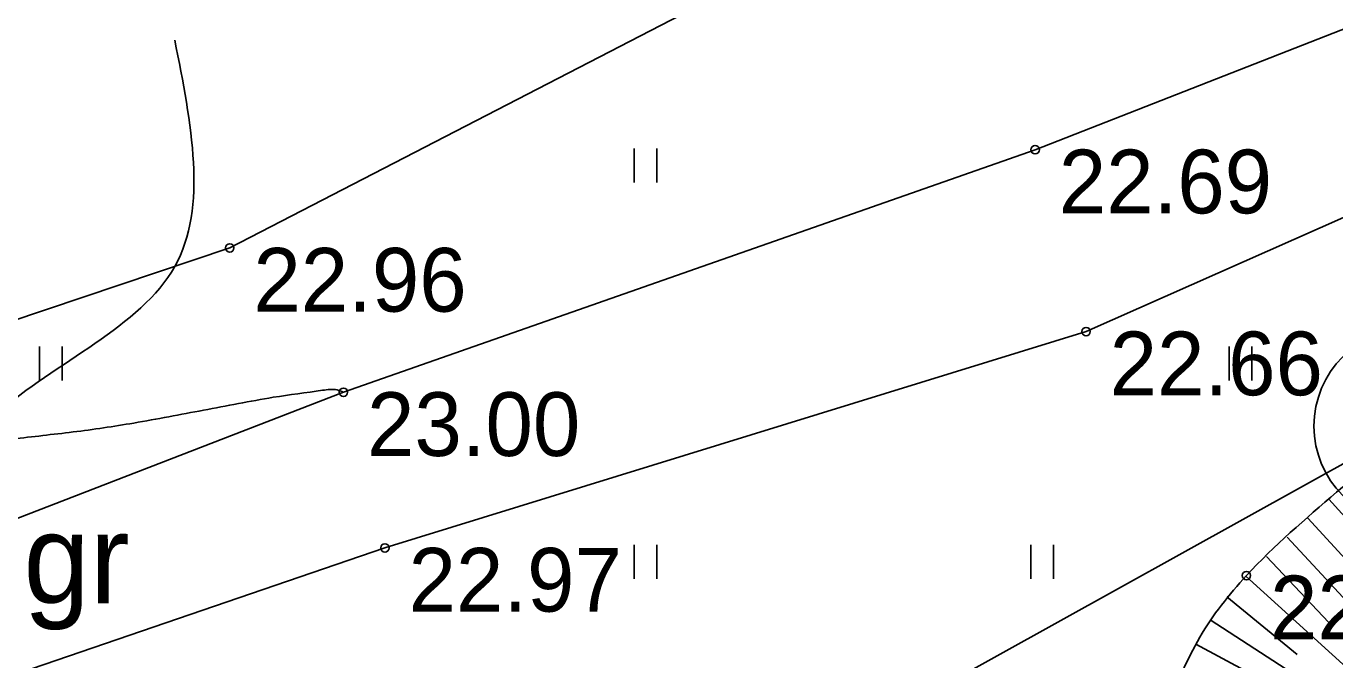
# Model space of a CAD drawing. Extents: x 521824 to 524158, y 294774 to 296228.
# Drawn here: x 521968.76 to 521991.87, y 295983.07 to 295994.26 of the extents above; entities that cross this region are included whole.
import ezdxf

# ---------------------------------------------------------------- set-up
doc = ezdxf.new("R2010")
doc.units = 0
for name, color, linetype in [('CELI_CMAL_####_####_#', 7, 'Continuous'), ('CELI_CSEG_####_TKST_#', 7, 'Continuous'), ('GL Atradnes kontura', 7, 'Continuous'), ('GL Atradnes Robezpunkti', 7, 'Continuous'), ('HIDG_HORZ_RESN_####_#', 7, 'Continuous'), ('RAMI_UZMR_####_####_#', 7, 'Continuous'), ('RELJ_AATZ_####_TKST_#', 7, 'Continuous'), ('RELJ_ELEM_####_####_#', 7, 'Continuous'), ('RELJ_HORZ_PAMT_####_#', 7, 'Continuous'), ('RELJ_NOGA_####_####_#', 7, 'Continuous'), ('TERT_ELEM_####_####_#', 7, 'Continuous')]:
    doc.layers.add(name, color=color, linetype=linetype)

msp = doc.modelspace()

# ---------------------------------------------------------------- linework, layer by layer
at = {"layer": 'CELI_CMAL_####_####_#'}
for points in [[(522016.926, 296038.306), (522019.291, 296036.109), (522026.144, 296024.408), (522024.611, 296016.559), (522016.21, 296007.977), (522009.446, 296002.958), (521998.646, 295996.811), (521986.577, 295992.078), (521974.364, 295987.793), (521962.15, 295983.065), (521949.049, 295978.089), (521936.439, 295973.322), (521922.423, 295968.209), (521916.609, 295966.986)], [(521919.307, 295961.099), (521923.436, 295965.418), (521936.98, 295970.41), (521950.344, 295975.897), (521962.84, 295980.846), (521975.098, 295985.044), (521987.475, 295988.865), (521999.923, 295994.382), (522010.781, 296000.817), (522017.822, 296005.998), (522028.512, 296014.094), (522032.708, 296013.095), (522037.117, 296005.565), (522042.629, 295993.246), (522047.854, 295977.085), (522048.272, 295975.108), (522050.6, 295963.95), (522058.017, 295953.029), (522071.017, 295938.84), (522077.076, 295928.039), (522079.604, 295917.159), (522079.604, 295917.159)]]:
    msp.add_lwpolyline(points, dxfattribs=at)
at = {"layer": 'GL Atradnes kontura'}
msp.add_lwpolyline([(521873.3, 295920.729), (521993.224, 295987.196), (522041.36, 296024.307), (522231.747, 296043.148), (522231.747, 296043.148), (522324.238, 295937.68), (522172.848, 295833.392), (522160.802, 295825.572), (522154.447, 295832.015), (522095.923, 295791.504), (521999.655, 295722.606), (521986.667, 295713.792), (521905.108, 295850.089)], close=True, dxfattribs=at)
at = {"layer": 'GL Atradnes Robezpunkti'}
msp.add_circle((521993.224, 295987.196), 1.725, dxfattribs=at)
at = {"layer": 'HIDG_HORZ_RESN_####_#'}
msp.add_spline([(521991.098, 295970.584), (521991.361, 295971.278), (521991.544, 295971.992), (521991.631, 295972.636), (521991.67, 295973.287), (521991.708, 295973.937), (521991.792, 295974.583), (521992.63, 295977.225), (521993.211, 295978.366), (521993.867, 295979.444), (521995.485, 295981.37), (521997.019, 295982.765), (521998.585, 295984.11), (522000.189, 295985.403), (522001.836, 295986.644), (522003.976, 295988.175), (522005.153, 295988.977), (522005.573, 295989.274), (522005.842, 295989.418), (522006.142, 295989.64), (522006.471, 295989.666), (522006.478, 295989.599), (522006.466, 295989.526), (522006.399, 295989.37), (522006.201, 295989.063), (522005.975, 295988.711), (522005.731, 295988.372), (522004.942, 295987.535), (522004.639, 295987.117), (522004.481, 295986.733), (522004.423, 295986.398), (522004.378, 295986.007), (522004.399, 295985.686), (522004.471, 295985.525), (522004.59, 295985.595), (522004.709, 295985.673), (522004.948, 295985.833), (522005.409, 295986.135), (522005.803, 295986.452), (522006.182, 295986.785), (522006.909, 295987.485), (522008.327, 295988.922), (522009.25, 295989.823), (522010.176, 295990.722), (522012.8, 295992.885), (522014.764, 295994.23), (522015.821, 295994.628), (522016.98, 295994.792), (522018.134, 295994.975), (522019.175, 295995.425), (522019.869, 295995.953), (522020.532, 295996.498), (522021.781, 295997.642), (522022.943, 295998.856), (522024.04, 296000.142), (522024.659, 296000.936), (522025.232, 296001.756), (522025.813, 296002.577), (522026.455, 296003.378), (522027.623, 296004.465), (522028.262, 296004.882), (522028.898, 296005.162), (522029.797, 296005.281)], degree=3, dxfattribs=at)
at = {"layer": 'RAMI_UZMR_####_####_#'}
msp.add_lwpolyline([(521884.951, 295833.479), (521880.617, 295845.248), (521870.086, 295867.104), (521860.21, 295884.107), (521842.62, 295911.756), (521831.61, 295926.961), (521828.312, 295927.865), (521830.005, 295934.14), (521828.66, 295939.141), (521854.064, 295946.907), (521876.684, 295957.669), (521889.204, 295963.079), (521933.742, 295979.544), (521953.527, 295984.007), (521972.358, 295990.342), (521984.5, 295996.619), (522023.729, 296021.723)], dxfattribs=at)
at = {"layer": 'RELJ_ELEM_####_####_#'}
for centre in [(521986.577, 295992.078), (521972.358, 295990.342), (521987.475, 295988.865), (521974.364, 295987.793), (521975.098, 295985.044), (521990.306, 295984.555)]:
    msp.add_circle(centre, 0.075, dxfattribs=at)
at = {"layer": 'RELJ_HORZ_PAMT_####_#'}
msp.add_spline([(521971.387, 295994.015), (521971.387, 295990.015), (521968.248, 295987.412), (521968.164, 295987.335), (521968.083, 295987.24), (521968.053, 295987.069), (521968.165, 295987.012), (521968.282, 295986.979), (521968.52, 295986.973), (521969.057, 295987.029), (521969.593, 295987.092), (521970.129, 295987.165), (521970.663, 295987.25), (521971.28, 295987.361), (521971.895, 295987.477), (521972.51, 295987.593), (521973.127, 295987.704), (521973.996, 295987.828), (521974.255, 295987.834), (521974.364, 295987.793)], degree=3, dxfattribs=at)
at = {"layer": 'RELJ_NOGA_####_####_#'}
for p, q in [((521991.763, 295985.907), (521995.223, 295982.049)), ((521991.392, 295985.572), (521992.449, 295984.415)), ((521991.025, 295985.233), (521994.607, 295981.372)), ((521990.66, 295984.892), (521991.755, 295983.736)), ((521990.298, 295984.547), (521994.243, 295980.961)), ((521989.96, 295984.178), (521991.201, 295983.163)), ((521989.667, 295983.774), (521994.156, 295980.862)), ((521989.415, 295983.342), (521990.825, 295982.584))]:
    msp.add_line(p, q, dxfattribs=at)
msp.add_spline([(522004.959, 295994.763), (522004.669, 295994.618), (522001.953, 295993.298), (521999.283, 295991.897), (521997.991, 295991.121), (521997.361, 295990.706), (521996.743, 295990.27), (521995.097, 295988.9), (521993.516, 295987.455), (521991.899, 295986.028), (521990.306, 295984.555), (521989.484, 295983.468), (521988.925, 295982.206), (521988.502, 295980.867), (521988.303, 295980.201), (521988.089, 295979.552), (521987.627, 295977.511), (521987.453, 295975.366), (521987.309, 295973.233), (521987.176, 295972.225), (521987.068, 295971.725), (521986.936, 295971.227), (521986.631, 295970.771), (521986.092, 295970.469), (521984.613, 295970.296), (521983.113, 295970.636), (521982.547, 295970.976), (521982.204, 295971.417), (521982.165, 295971.604), (521982.175, 295971.806), (521982.331, 295972.172), (521982.97, 295972.974), (521983.604, 295973.781), (521983.714, 295974.554), (521983.324, 295975.398), (521982.883, 295976.235), (521982.376, 295977.059), (521981.79, 295977.861)], degree=3, dxfattribs=at)
at = {"layer": 'TERT_ELEM_####_####_#'}
for p, q in [((521979.5, 295991.5), (521979.5, 295992.1)), ((521979.9, 295991.5), (521979.9, 295992.1)), ((521969, 295988), (521969, 295988.6)), ((521969.4, 295988), (521969.4, 295988.6)), ((521990, 295988), (521990, 295988.6)), ((521990.4, 295988), (521990.4, 295988.6)), ((521979.5, 295984.5), (521979.5, 295985.1)), ((521979.9, 295984.5), (521979.9, 295985.1)), ((521986.5, 295984.5), (521986.5, 295985.1)), ((521986.9, 295984.5), (521986.9, 295985.1))]:
    msp.add_line(p, q, dxfattribs=at)

# ---------------------------------------------------------------- texts
at = {"layer": 'CELI_CSEG_####_TKST_#'}
msp.add_text('gr', height=1.575, dxfattribs=at).set_placement((521968.717, 295984.067))
at = {"layer": 'RELJ_AATZ_####_TKST_#'}
for s, p in [(' 22.69', (521986.577, 295990.953)), (' 22.96', (521972.358, 295989.217)), (' 22.66', (521987.475, 295987.74)), (' 23.00', (521974.364, 295986.668)), (' 22.97', (521975.098, 295983.919)), (' 22.58', (521990.306, 295983.43))]:
    msp.add_text(s, height=1.125, dxfattribs=at).set_placement(p)

doc.saveas('drawing.dxf')
